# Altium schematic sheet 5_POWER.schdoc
size 307 x 218 mm; Symbol: Sheet-Symbol_A4; Device: Sheet-Symbol_A4; @Project Name: Hexapod; @Page Count: 5; @Update Date: 2024-12-17; @Create Date: 2024-10-18; @Schematic Name: Schematic1; @Page No: 5; @Page Name: POWER; Company: EasyEDA.com; Version: V1.0; Page Size: A4; @Create Time: 15:03:33; @Update Time: 14:42:09; Title Block Position: 3; Width: 1170; Height: 825; Region Start: 1; X Region Count: 6; Y Region Count: 4; Blade Width: 10; @Board Name: Hexapod
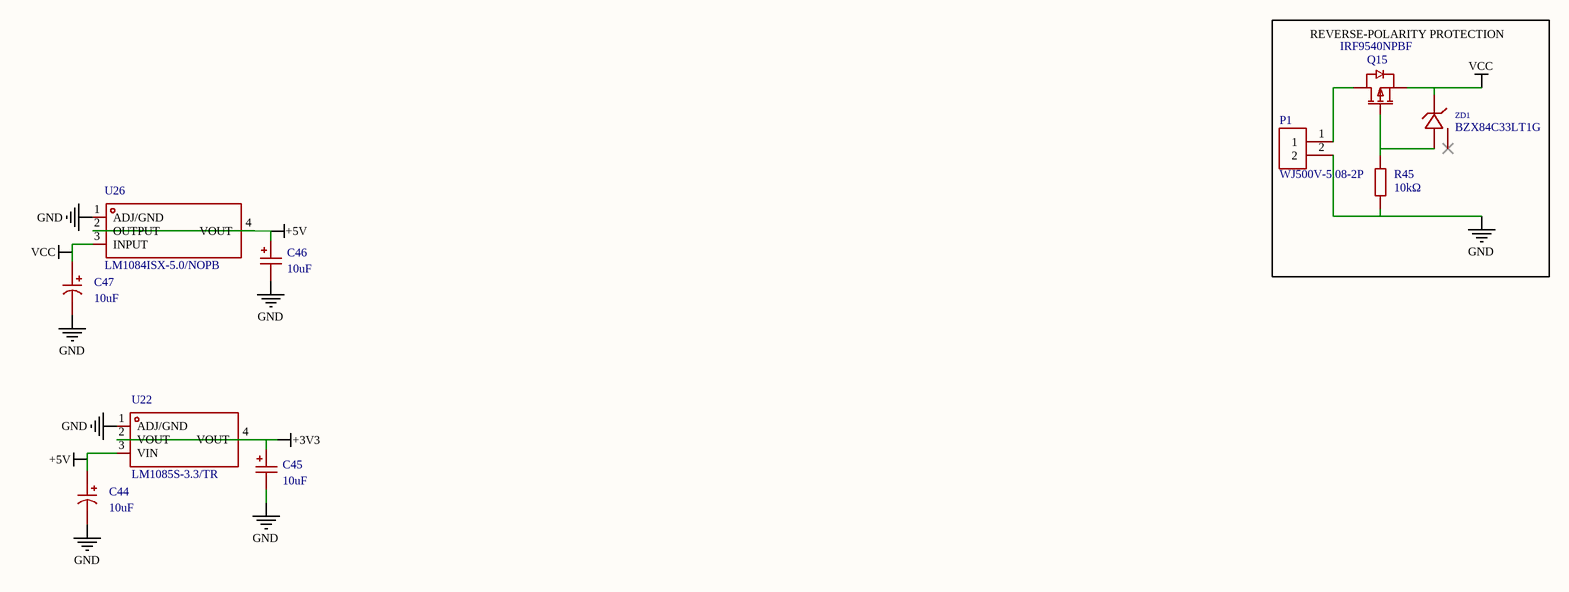
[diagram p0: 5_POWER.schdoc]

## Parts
C44  10uF  [CAP-SMD_BD4.0-L4.3-W4.3-FD]
C45  10uF  [CAP-SMD_L3.2-W1.6-RD-C7171]
C46  10uF  [CAP-SMD_L3.2-W1.6-RD-C7171]
C47  10uF  [CAP-SMD_BD4.0-L4.3-W4.3-FD]
P1  WJ500V-5.08-2P  [CONN-TH_2P-P5.00_WJ500V-5.08-2P]
Q15  IRF9540NPBF  [TO-220-3_L10.0-W4.5-P2.54-L]
R45  10kΩ  [R0402]
U22  LM1085S-3.3/TR  [TO-263-3_L8.6-W10.2-P2.54-LS14.4-BR]
U26  LM1084ISX-5.0/NOPB  [TO-263-3_L10.2-W8.6-P2.54-LS14.4-TL]
ZD1  BZX84C33LT1G  [SOT-23-3_L2.9-W1.6-P1.90-LS2.8-BR]

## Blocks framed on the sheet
REVERSE-POLARITY PROTECTION: P1 Q15 R45 ZD1

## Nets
+3V3: C45.1 U22.2(VOUT) U22.4(VOUT)
+5V: C44.1 C46.1 U22.3(VIN) U26.2(OUTPUT) U26.4(VOUT)
GND: C44.2 C45.2 C46.2 C47.2 P1.2 R45.1 U22.1(ADJ/GND) U26.1(ADJ/GND)
VCC: C47.1 Q15.3(S) U26.3(INPUT) ZD1.3(K)
NetP1_1: P1.1 Q15.2(D)
NetQ15_1: Q15.1(G) R45.2 ZD1.1(A)

Not connected (* = marked no-connect by the designer): ZD1 2(nc)*

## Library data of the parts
C44 C47 = RST10UF16V013: Manufacturer: KNSCHA(科尼盛); Add into BOM: yes; Tolerance: ±20%; Ripple Current: 14mA@120Hz; Lifetime @ Temp: 2000hrs@105℃
C45 C46 = TAJA106K016RNJ: Manufacturer: Kyocera AVX; Add into BOM: yes; Tolerance: ±10%; Equivalent Series Resistance(ESR): 3Ω@100kHz
P1 = WJ500V-5.08-2P: Manufacturer: KANGNEX(康奈克斯电气); Symbol: WJ500V-5.08-2P-14-00A; Add into BOM: yes; Structure: 1x2P; Pitch: 5.08mm; Current Rating (Max): 18A; Voltage Rating (Max): 250V; Wire Gauge - AWG: 14~30; Wire Gauge - mm2: 2.5; Number of PINs Per Row: 2; Screw Specification: M2.5
Q15 = IRF9540NPBF: Manufacturer: Infineon(英飞凌); Add into BOM: yes; Type: 1个PChannel; Drain Source On Resistance (RDS(on)@Vgs,Id): 117mΩ@10V,11A; Gate Threshold Voltage (Vgs(th)@Id): 4V@250uA; Total Gate Charge (Qg@Vgs): 97nC@10V; Input Capacitance (Ciss@Vds): 1.3nF@25V
R45 = RC0402FR-0710KL: Manufacturer: YAGEO(国巨); Add into BOM: yes; Tolerance: ±1%; Temperature Coefficient: ±100ppm/℃
U22 = LM1085S-3.3/TR: Manufacturer: HGSEMI(华冠); Add into BOM: yes; Maximum Input Voltage: 15V; Output Voltage: 3.3V; MAX Output Current: 3A; Power Supply Rejection Ratio (PSRR): 65dB@(120Hz); Dropout Voltage: 1.5V@(3A); Output Polarity: Positive electrode; Number of Outputs: 1
U26 = LM1084ISX-5.0/NOPB: Manufacturer: TI(德州仪器); Add into BOM: yes; Output Type: Fixed; Maximum Input Voltage: 25V; Output Voltage: 5V; Output Current: 5A; Power Supply Rejection Ratio (PSRR): 68dB@(120Hz); Dropout Voltage: 1.5V@(5A); standby current: 10mA; Output Polarity: Positive electrode; Number of Outputs: 1
ZD1 = BZX84C33LT1G: Manufacturer: onsemi(安森美); Add into BOM: yes; Diode Configuration: Single; Zener Voltage (Nom): 33V; Reverse Leakage Current (Ir): 50nA@23.1V; Zener Voltage (Range): 31V~35V; Power Dissipation: 225mW; Zener Impedance (Zzt): 80Ω; Tolerance: ±6%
